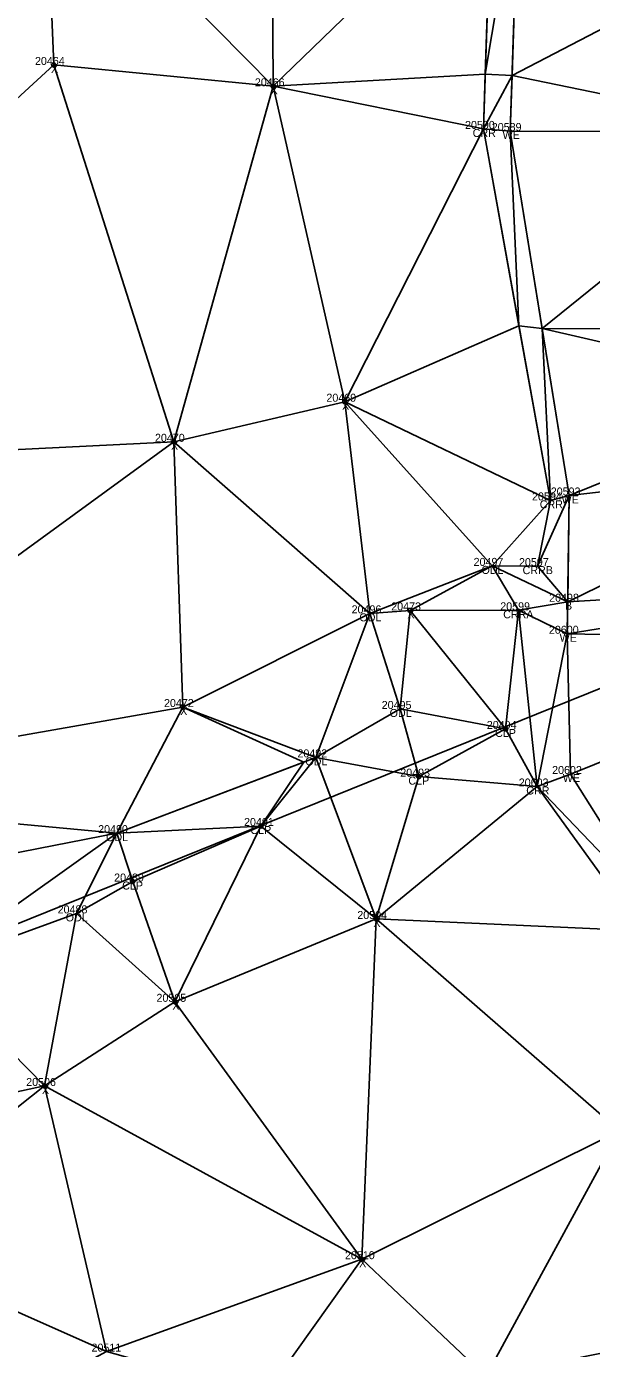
# Model space of a CAD drawing. Extents: x 1966740 to 1969291, y 1117379 to 1118460.
# Drawn here: x 1967732.8 to 1967803.4, y 1117783.2 to 1117948.4 of the extents above; entities that cross this region are included whole.
import ezdxf

# ---------------------------------------------------------------- set-up
doc = ezdxf.new("R2010")
doc.units = 0
for name, color, linetype in [('Level 1', 7, 'Continuous'), ('Level 10', 7, 'Continuous'), ('Level 30', 7, 'Continuous'), ('Level 35', 7, 'Continuous'), ('Level 50', 7, 'Continuous'), ('Level 52', 7, 'Continuous'), ('Level 56', 7, 'Continuous'), ('Level 6', 7, 'Continuous'), ('Level 60', 7, 'Continuous'), ('Level 61', 7, 'Continuous'), ('Level 62', 7, 'Continuous')]:
    doc.layers.add(name, color=color, linetype=linetype)

msp = doc.modelspace()

# ---------------------------------------------------------------- linework, layer by layer
at = {"layer": 'Level 1'}
msp.add_line((1966770.74, 1117448.12), (1967849.47, 1117883.86), dxfattribs=at)
at = {"layer": 'Level 10'}
for points in [[(1967848.54, 1118347.45), (1967880.38, 1118337.78), (1967886.93, 1118331.58), (1967896.4, 1118282.85), (1967906.33, 1118232.39), (1967914.38, 1118193.81), (1967904.29, 1118181.59), (1967847.52, 1118139.25), (1967823.99, 1118093.05), (1967800.15, 1118046.69), (1967791.83, 1117992.41), (1967789.93, 1117935.61), (1967798.32, 1117889.19), (1967796.67, 1117880.97)], [(1967849.83, 1118135.18), (1967825.91, 1118086.77), (1967802.99, 1118041.98), (1967795.15, 1117992.28), (1967793.27, 1117935.35), (1967800.64, 1117889.8), (1967800.4, 1117872.52), (1967800.8, 1117854.99), (1967811.67, 1117837.73), (1967837.15, 1117809.04), (1967808.01, 1117752.12), (1967788.48, 1117706.78), (1967783.36, 1117689.17), (1967764.63, 1117648.93), (1967738.42, 1117613.44), (1967731.11, 1117607.31), (1967718.77, 1117573.47), (1967736.01, 1117517.29), (1967781.71, 1117484.69), (1967799.34, 1117478.73), (1967814.43, 1117469.18)], [(1967794.3, 1117875.45), (1967796.63, 1117853.43), (1967809.67, 1117835.4), (1967828.83, 1117808.28), (1967805.08, 1117754.56), (1967786.33, 1117708.04), (1967780.19, 1117689.35), (1967762.68, 1117651.19), (1967736.39, 1117616.3), (1967727.33, 1117611.21), (1967715.04, 1117573.35), (1967731.01, 1117514.73), (1967775.86, 1117468.11), (1967793.29, 1117458.88), (1967816.39, 1117454.18)]]:
    msp.add_lwpolyline(points, dxfattribs=at)
at = {"layer": 'Level 30'}
for centre in [(1967736.25, 1117943.61), (1967763.67, 1117940.94), (1967772.6, 1117901.52), (1967751.24, 1117896.51), (1967780.76, 1117875.44), (1967752.37, 1117863.36), (1967792.7, 1117860.62), (1967781.85, 1117854.66), (1967762.13, 1117848.49), (1967746.11, 1117841.55), (1967776.52, 1117836.87), (1967751.39, 1117826.52), (1967735.1, 1117816), (1967774.73, 1117794.35)]:
    msp.add_circle(centre, 0.25, dxfattribs=at)
at = {"layer": 'Level 35'}
for points in [[(1967735.17, 1117969.82), (1967763.46, 1117974.91), (1967763.67, 1117940.94)], [(1967763.46, 1117974.91), (1967790.99, 1117967.42), (1967763.67, 1117940.94)], [(1967681.25, 1117893.06), (1967735.17, 1117969.82), (1967736.25, 1117943.61)], [(1967735.17, 1117969.82), (1967763.67, 1117940.94), (1967736.25, 1117943.61)], [(1967763.67, 1117940.94), (1967790.99, 1117967.42), (1967790.15, 1117942.44)], [(1967790.15, 1117942.44), (1967790.99, 1117967.42), (1967794.33, 1117967.29)], [(1967790.15, 1117942.44), (1967794.33, 1117967.29), (1967793.5, 1117942.3)], [(1967793.5, 1117942.3), (1967794.33, 1117967.29), (1967827.33, 1117959.9)], [(1967793.5, 1117942.3), (1967827.33, 1117959.9), (1967827.73, 1117935.27)], [(1967681.25, 1117893.06), (1967736.25, 1117943.61), (1967751.24, 1117896.51)], [(1967736.25, 1117943.61), (1967763.67, 1117940.94), (1967751.24, 1117896.51)], [(1967763.67, 1117940.94), (1967790.15, 1117942.44), (1967789.93, 1117935.61)], [(1967789.93, 1117935.61), (1967790.15, 1117942.44), (1967793.5, 1117942.3)], [(1967789.93, 1117935.61), (1967793.5, 1117942.3), (1967793.27, 1117935.35)], [(1967793.27, 1117935.35), (1967793.5, 1117942.3), (1967827.73, 1117935.27)], [(1967751.24, 1117896.51), (1967763.67, 1117940.94), (1967772.6, 1117901.52)], [(1967763.67, 1117940.94), (1967789.93, 1117935.61), (1967772.6, 1117901.52)], [(1967772.6, 1117901.52), (1967789.93, 1117935.61), (1967794.37, 1117911.01)], [(1967789.93, 1117935.61), (1967793.27, 1117935.35), (1967794.37, 1117911.01)], [(1967793.27, 1117935.35), (1967827.73, 1117935.27), (1967797.26, 1117910.67)], [(1967793.27, 1117935.35), (1967797.26, 1117910.67), (1967794.37, 1117911.01)], [(1967797.26, 1117910.67), (1967827.73, 1117935.27), (1967831.26, 1117910.53)], [(1967772.6, 1117901.52), (1967794.37, 1117911.01), (1967798.32, 1117889.19)], [(1967794.37, 1117911.01), (1967797.26, 1117910.67), (1967798.32, 1117889.19)], [(1967797.26, 1117910.67), (1967831.26, 1117910.53), (1967832.39, 1117902.59)], [(1967797.26, 1117910.67), (1967832.39, 1117902.59), (1967800.64, 1117889.8)], [(1967797.26, 1117910.67), (1967800.64, 1117889.8), (1967798.32, 1117889.19)], [(1967800.64, 1117889.8), (1967832.39, 1117902.59), (1967835.81, 1117893.8)], [(1967751.24, 1117896.51), (1967772.6, 1117901.52), (1967775.75, 1117875.07)], [(1967772.6, 1117901.52), (1967798.32, 1117889.19), (1967791.02, 1117881)], [(1967772.6, 1117901.52), (1967791.02, 1117881), (1967775.75, 1117875.07)], [(1967681.25, 1117893.06), (1967751.24, 1117896.51), (1967690.95, 1117852.56)], [(1967690.95, 1117852.56), (1967751.24, 1117896.51), (1967752.37, 1117863.36)], [(1967751.24, 1117896.51), (1967775.75, 1117875.07), (1967752.37, 1117863.36)], [(1967800.46, 1117876.52), (1967800.64, 1117889.8), (1967835.81, 1117893.8)], [(1967800.46, 1117876.52), (1967835.81, 1117893.8), (1967839.64, 1117878.84)], [(1967791.02, 1117881), (1967798.32, 1117889.19), (1967796.67, 1117880.97)], [(1967796.67, 1117880.97), (1967798.32, 1117889.19), (1967800.64, 1117889.8)], [(1967796.67, 1117880.97), (1967800.64, 1117889.8), (1967800.46, 1117876.52)], [(1967775.75, 1117875.07), (1967791.02, 1117881), (1967780.76, 1117875.44)], [(1967780.76, 1117875.44), (1967791.02, 1117881), (1967794.3, 1117875.45)], [(1967791.02, 1117881), (1967796.67, 1117880.97), (1967800.46, 1117876.52)], [(1967791.02, 1117881), (1967800.46, 1117876.52), (1967794.3, 1117875.45)], [(1967800.4, 1117872.52), (1967800.46, 1117876.52), (1967839.64, 1117878.84)], [(1967800.4, 1117872.52), (1967839.64, 1117878.84), (1967842.37, 1117871.73)], [(1967794.3, 1117875.45), (1967800.46, 1117876.52), (1967800.4, 1117872.52)], [(1967752.37, 1117863.36), (1967775.75, 1117875.07), (1967769.01, 1117857.07)], [(1967769.01, 1117857.07), (1967775.75, 1117875.07), (1967779.54, 1117863.12)], [(1967775.75, 1117875.07), (1967780.76, 1117875.44), (1967779.54, 1117863.12)], [(1967779.54, 1117863.12), (1967780.76, 1117875.44), (1967792.7, 1117860.62)], [(1967780.76, 1117875.44), (1967794.3, 1117875.45), (1967792.7, 1117860.62)], [(1967792.7, 1117860.62), (1967794.3, 1117875.45), (1967796.63, 1117853.43)], [(1967794.3, 1117875.45), (1967800.4, 1117872.52), (1967796.63, 1117853.43)], [(1967796.63, 1117853.43), (1967800.4, 1117872.52), (1967800.8, 1117854.99)], [(1967800.4, 1117872.52), (1967842.37, 1117871.73), (1967800.8, 1117854.99)], [(1967800.8, 1117854.99), (1967842.37, 1117871.73), (1967811.67, 1117837.73)], [(1967690.95, 1117852.56), (1967752.37, 1117863.36), (1967744.11, 1117847.6)], [(1967744.11, 1117847.6), (1967752.37, 1117863.36), (1967767.48, 1117856.48)], [(1967752.37, 1117863.36), (1967769.01, 1117857.07), (1967767.48, 1117856.48)], [(1967769.01, 1117857.07), (1967779.54, 1117863.12), (1967781.85, 1117854.66)], [(1967779.54, 1117863.12), (1967792.7, 1117860.62), (1967781.85, 1117854.66)], [(1967781.85, 1117854.66), (1967792.7, 1117860.62), (1967796.63, 1117853.43)], [(1967744.11, 1117847.6), (1967767.48, 1117856.48), (1967762.13, 1117848.49)], [(1967762.13, 1117848.49), (1967767.48, 1117856.48), (1967769.01, 1117857.07)], [(1967762.13, 1117848.49), (1967769.01, 1117857.07), (1967776.52, 1117836.87)], [(1967769.01, 1117857.07), (1967781.85, 1117854.66), (1967776.52, 1117836.87)], [(1967776.52, 1117836.87), (1967781.85, 1117854.66), (1967796.63, 1117853.43)], [(1967796.63, 1117853.43), (1967800.8, 1117854.99), (1967811.67, 1117837.73)], [(1967776.52, 1117836.87), (1967796.63, 1117853.43), (1967809.67, 1117835.4)], [(1967796.63, 1117853.43), (1967811.67, 1117837.73), (1967809.67, 1117835.4)], [(1967690.95, 1117852.56), (1967744.11, 1117847.6), (1967700.5, 1117839.06)], [(1967744.11, 1117847.6), (1967762.13, 1117848.49), (1967746.11, 1117841.55)], [(1967746.11, 1117841.55), (1967762.13, 1117848.49), (1967751.39, 1117826.52)], [(1967751.39, 1117826.52), (1967762.13, 1117848.49), (1967776.52, 1117836.87)], [(1967700.5, 1117839.06), (1967744.11, 1117847.6), (1967720.54, 1117830.82)], [(1967720.54, 1117830.82), (1967744.11, 1117847.6), (1967739.07, 1117837.57)], [(1967739.07, 1117837.57), (1967744.11, 1117847.6), (1967746.11, 1117841.55)], [(1967739.07, 1117837.57), (1967746.11, 1117841.55), (1967751.39, 1117826.52)], [(1967720.54, 1117830.82), (1967739.07, 1117837.57), (1967735.1, 1117816)], [(1967735.1, 1117816), (1967739.07, 1117837.57), (1967751.39, 1117826.52)], [(1967751.39, 1117826.52), (1967776.52, 1117836.87), (1967774.73, 1117794.35)], [(1967774.73, 1117794.35), (1967776.52, 1117836.87), (1967806.95, 1117810.4)], [(1967776.52, 1117836.87), (1967809.67, 1117835.4), (1967806.95, 1117810.4)], [(1967709.93, 1117810.55), (1967720.54, 1117830.82), (1967735.1, 1117816)], [(1967735.1, 1117816), (1967751.39, 1117826.52), (1967774.73, 1117794.35)], [(1967709.93, 1117810.55), (1967735.1, 1117816), (1967711.06, 1117796.94)], [(1967711.06, 1117796.94), (1967735.1, 1117816), (1967742.85, 1117782.8)], [(1967735.1, 1117816), (1967774.73, 1117794.35), (1967742.85, 1117782.8)], [(1967774.73, 1117794.35), (1967806.95, 1117810.4), (1967790.23, 1117779.71)], [(1967790.23, 1117779.71), (1967806.95, 1117810.4), (1967818.72, 1117785.42)], [(1967695.23, 1117757.03), (1967711.06, 1117796.94), (1967742.85, 1117782.8)], [(1967742.85, 1117782.8), (1967774.73, 1117794.35), (1967762.56, 1117777.29)], [(1967762.56, 1117777.29), (1967774.73, 1117794.35), (1967790.23, 1117779.71)]]:
    msp.add_lwpolyline(points, close=True, dxfattribs=at)
at = {"layer": 'Level 50'}
for centre in [(1967789.93, 1117935.61), (1967793.27, 1117935.35), (1967798.32, 1117889.19), (1967800.64, 1117889.8), (1967791.02, 1117881), (1967796.67, 1117880.97), (1967800.46, 1117876.52), (1967775.75, 1117875.07), (1967794.3, 1117875.45), (1967800.4, 1117872.52), (1967779.54, 1117863.12), (1967769.01, 1117857.07), (1967800.8, 1117854.99), (1967796.63, 1117853.43), (1967744.11, 1117847.6), (1967739.07, 1117837.57)]:
    msp.add_circle(centre, 0.001, dxfattribs=at)
at = {"layer": 'Level 6'}
msp.add_lwpolyline([(1967720.54, 1117830.82), (1967739.07, 1117837.57), (1967744.11, 1117847.6), (1967769.01, 1117857.07), (1967779.54, 1117863.12), (1967775.75, 1117875.07), (1967791.02, 1117881), (1967800.46, 1117876.52)], dxfattribs=at)

# ---------------------------------------------------------------- texts
at = {"layer": 'Level 52'}
for s, p in [('20464', (1967733.9, 1117943.61)), ('20466', (1967761.37, 1117940.94)), ('20469', (1967770.31, 1117901.52)), ('20470', (1967748.89, 1117896.51)), ('20473', (1967778.41, 1117875.44)), ('20472', (1967750.02, 1117863.36)), ('20494', (1967790.35, 1117860.62)), ('20493', (1967779.54, 1117854.66)), ('20491', (1967760.02, 1117848.49)), ('20489', (1967743.79, 1117841.55)), ('20504', (1967774.17, 1117836.87)), ('20505', (1967749.08, 1117826.52)), ('20506', (1967732.8, 1117816)), ('20510', (1967772.63, 1117794.35)), ('20511', (1967740.96, 1117782.8))]:
    msp.add_text(s, height=1, dxfattribs=at).set_placement(p)
at = {"layer": 'Level 56'}
for s, p in [('20497', (1967788.7, 1117881)), ('ODL', (1967789.69, 1117880)), ('20496', (1967773.46, 1117875.07)), ('20498', (1967798.14, 1117876.52)), ('B', (1967800.12, 1117875.52)), ('ODL', (1967774.43, 1117874.07)), ('20495', (1967777.22, 1117863.12)), ('ODL', (1967778.21, 1117862.12)), ('20492', (1967766.69, 1117857.07)), ('ODL', (1967767.68, 1117856.07)), ('20490', (1967741.79, 1117847.6)), ('ODL', (1967742.78, 1117846.6)), ('20488', (1967736.73, 1117837.57)), ('ODL', (1967737.74, 1117836.57))]:
    msp.add_text(s, height=1, dxfattribs=at).set_placement(p)
at = {"layer": 'Level 60'}
for s, p in [('CRR', (1967788.58, 1117934.61)), ('WE', (1967792.32, 1117934.35)), ('CRR', (1967796.97, 1117888.19)), ('WE', (1967799.69, 1117888.8)), ('CRRB', (1967794.82, 1117879.97)), ('CRRA', (1967792.4, 1117874.45)), ('WE', (1967799.45, 1117871.52)), ('WE', (1967799.85, 1117853.99)), ('CRR', (1967795.28, 1117852.43))]:
    msp.add_text(s, height=1, dxfattribs=at).set_placement(p)
at = {"layer": 'Level 61'}
for s, p in [('20590', (1967787.63, 1117935.61)), ('20589', (1967790.97, 1117935.35)), ('20594', (1967796, 1117889.19)), ('20593', (1967798.34, 1117889.8)), ('20597', (1967794.37, 1117880.97)), ('20599', (1967792.03, 1117875.45)), ('20600', (1967798.11, 1117872.52)), ('20602', (1967798.51, 1117854.99)), ('20603', (1967794.34, 1117853.43))]:
    msp.add_text(s, height=1, dxfattribs=at).set_placement(p)
at = {"layer": 'Level 62'}
for s, p in [('X', (1967735.91, 1117942.61)), ('X', (1967763.34, 1117939.94)), ('X', (1967772.27, 1117900.52)), ('X', (1967750.9, 1117895.51)), ('X', (1967780.43, 1117874.44)), ('X', (1967752.04, 1117862.36)), ('CLP', (1967791.39, 1117859.62)), ('CLP', (1967780.55, 1117853.66)), ('CLP', (1967760.82, 1117847.49)), ('CLP', (1967744.8, 1117840.55)), ('X', (1967776.18, 1117835.87)), ('X', (1967751.06, 1117825.52)), ('X', (1967734.77, 1117815)), ('X', (1967774.4, 1117793.35))]:
    msp.add_text(s, height=1, dxfattribs=at).set_placement(p)

doc.saveas('drawing.dxf')
